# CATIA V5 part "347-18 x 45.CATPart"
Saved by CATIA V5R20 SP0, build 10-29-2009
Part number: 347-18 x 45
Definition: NONE
Nomenclature: 347-18 x 45
Source: Unknown
Description: 347-18 x 45
Bounding box of the stored display mesh (mm): x 0 to 45, y -14 to 14, z -14 to 14
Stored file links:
  C:\Users\Utente\Desktop\IO LAVORO\3D X SITO CF\X SITO\3D files 347\347-18 x 45.CATPart
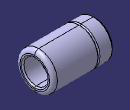
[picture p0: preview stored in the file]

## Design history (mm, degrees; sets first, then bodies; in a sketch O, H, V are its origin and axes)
Body1 "347-18 x 45" (main body)
  Solid1: solid without history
